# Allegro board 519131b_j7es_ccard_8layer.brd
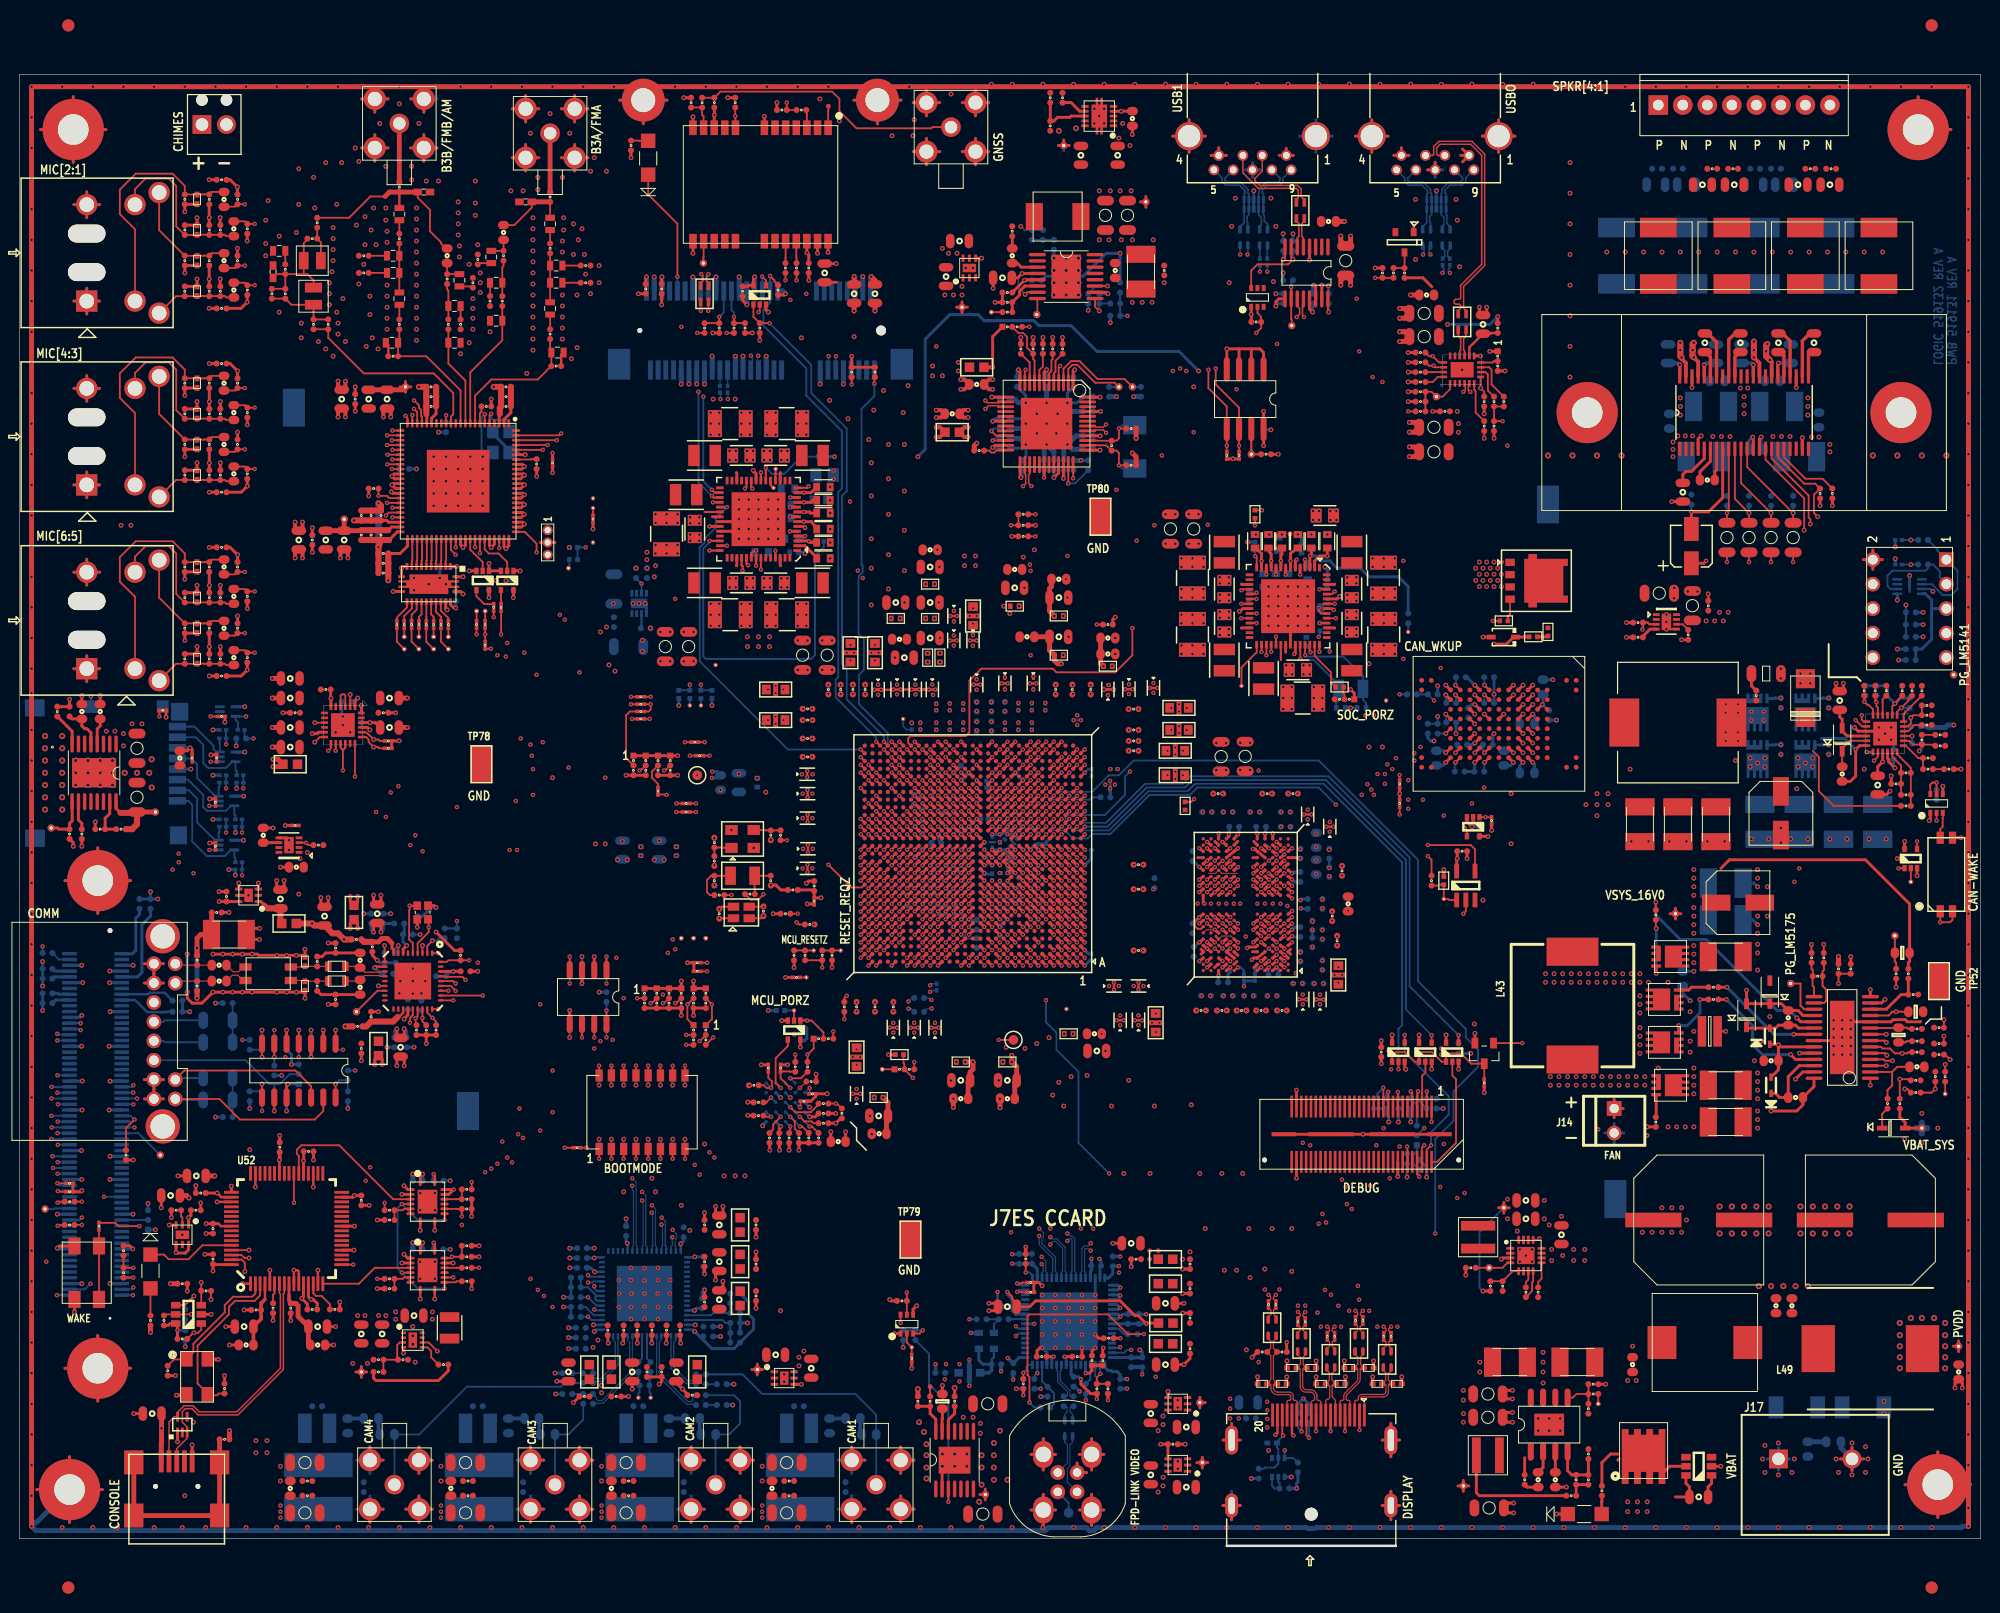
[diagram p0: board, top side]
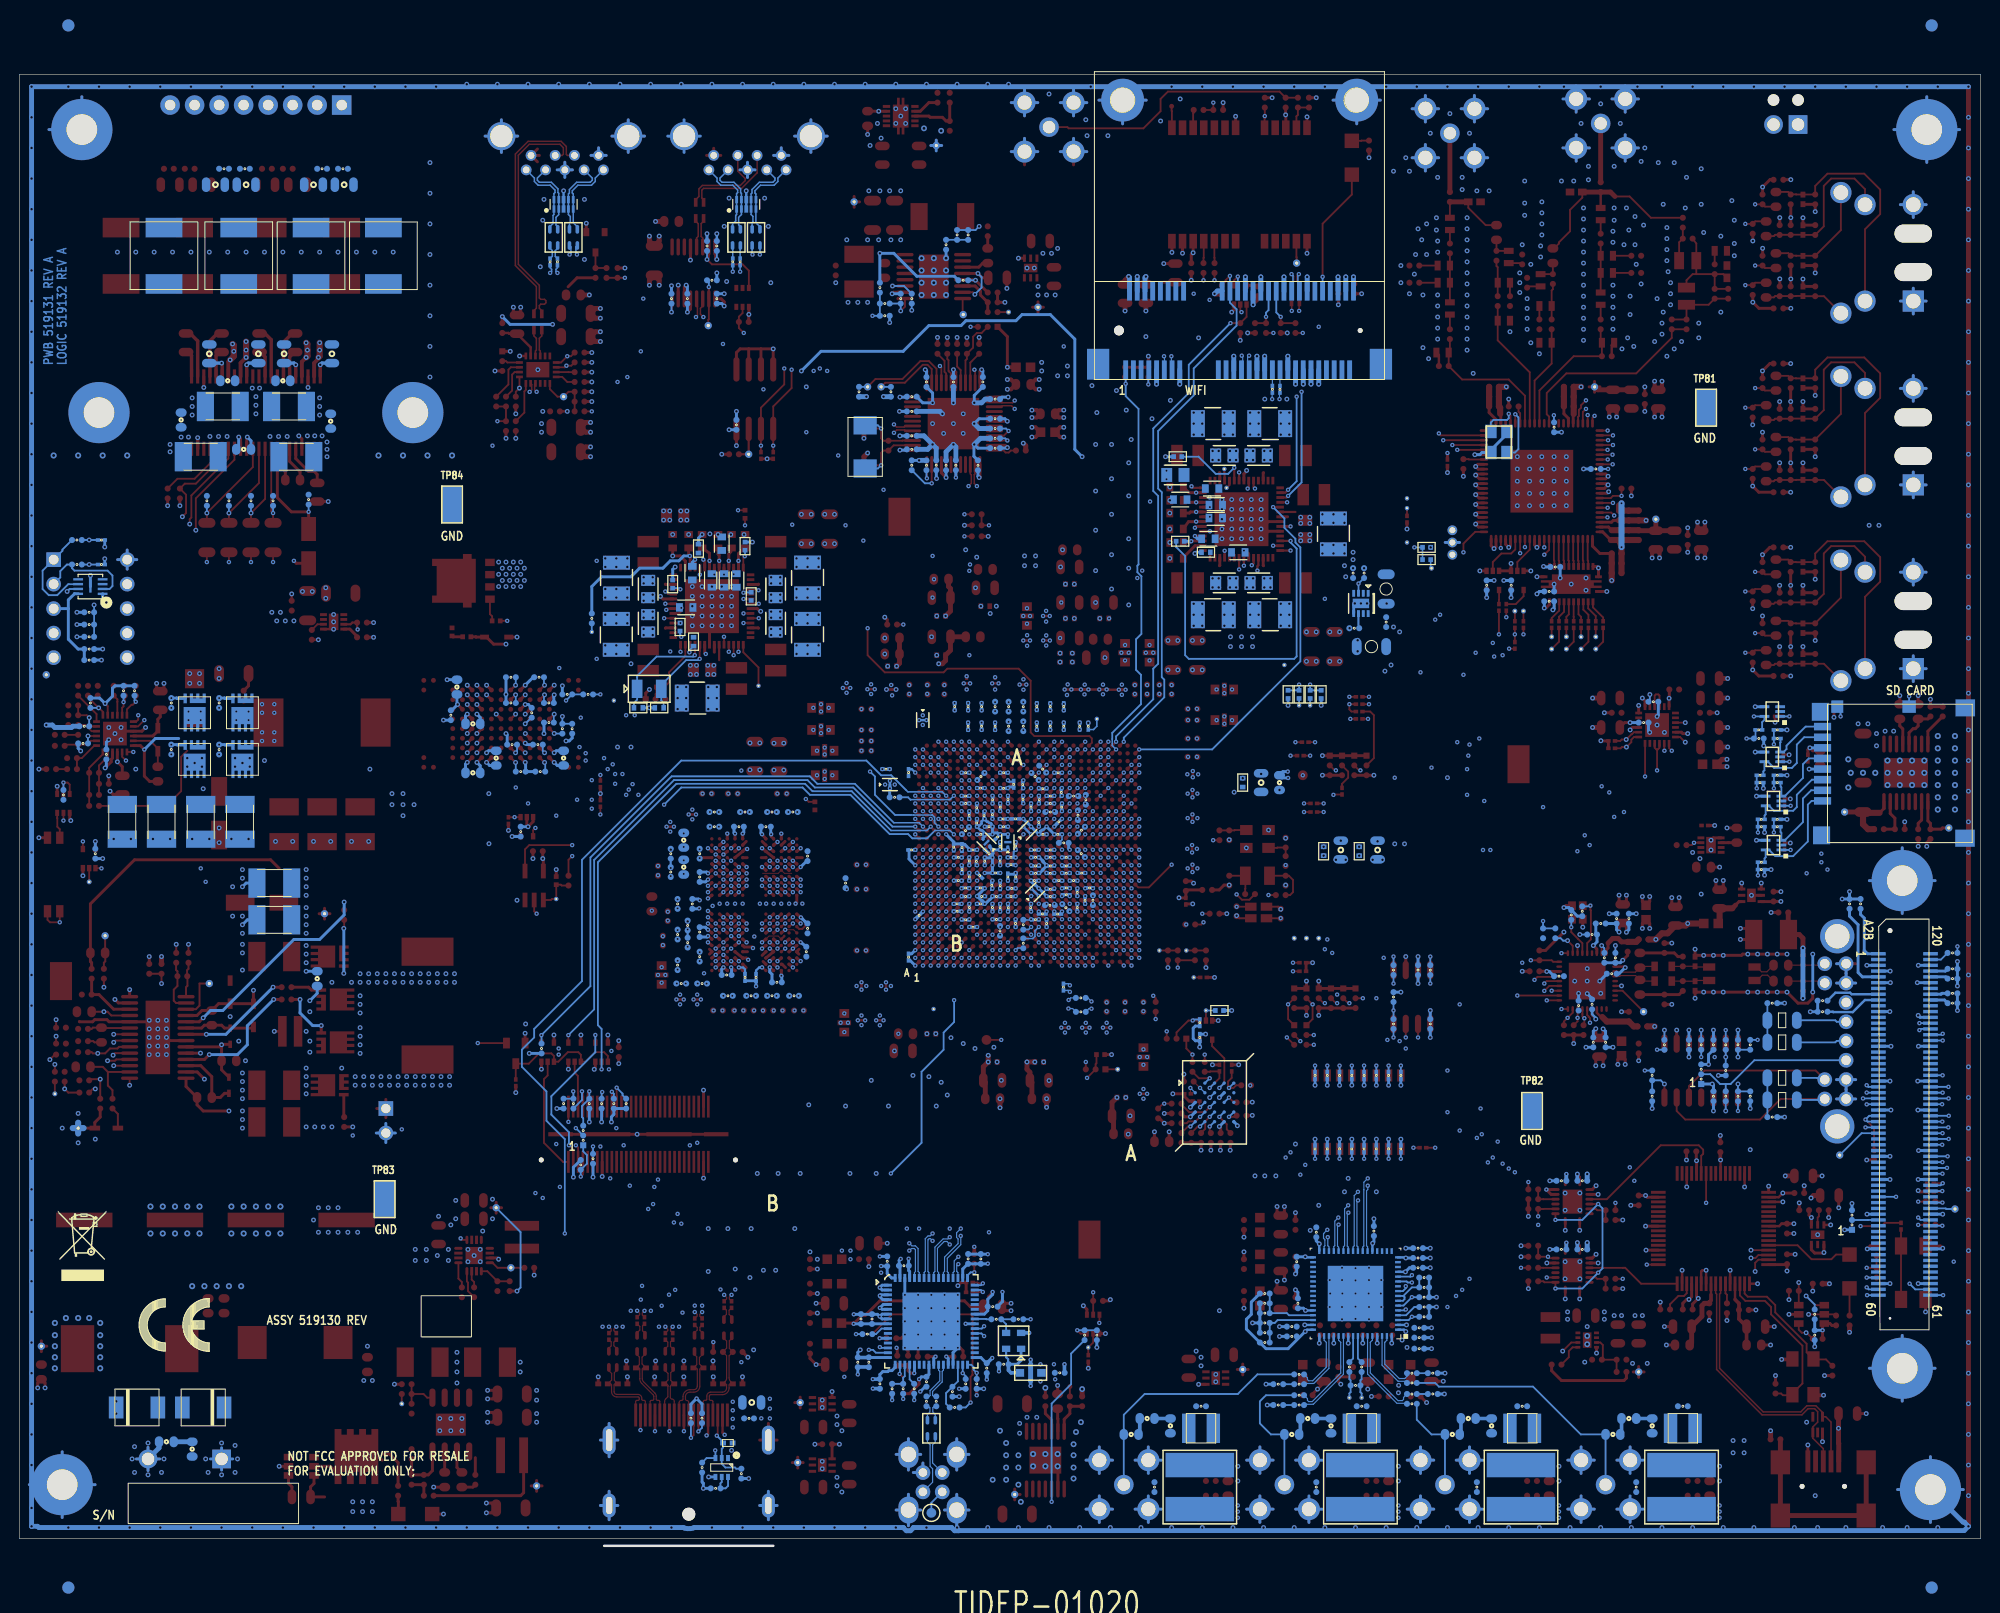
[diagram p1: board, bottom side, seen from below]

Outline 203.2 x 152.52 mm; copper layers: TOP, L2-SIGNAL, L3-GND, L4-SIGNAL, L5-SIGNAL, L6-PWR, L7-SIGNAL, BOTTOM. Coordinates in mm from the lower left corner of the outline.
Outline path: 0,152.52 0,0.75 203.2,0.75 203.2,152.52 0,152.52

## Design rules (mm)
net group C_DP0_TX0_N: nets C_DP0_TX0_N CON_DP0_TX0_N
net group C_PCIE0_TX0: nets C_PCIE0_TX0_N C_PCIE0_TX0_P
net group C_UB981_DOUT0: nets C_UB981_DOUT0_N C_UB981_DOUT0_P
net group C_USB_SS_TX1: nets C_USB1_SS_TX_N C_USB1_SS_TX_P
net group C_USB_SS_TX2: nets C_USB0_SS_TX_N C_USB0_SS_TX_P
net group CAM_0: nets CAM_0_N CAM_0_P
net group CAM_1: nets CAM_1_N CAM_1_P
net group CAM_2: nets CAM_2_N CAM_2_P
net group CAM_3: nets CAM_3_N CAM_3_P
net group CON_MMC1_CLK: nets CON_MMC1_CLK H_MMC1_CLK
net group CON_MMC1_DAT3: nets CON_MMC1_DAT3 H_MMC1_D3
net group CONN_USB1_DM: nets CONN_USB1_DM USB1_DM
net group CONN_USB1_DP: nets CONN_USB1_DP USB1_DP
net group CONN_USB2_D: nets CONN_USB2_DM CONN_USB2_DP
net group CONN_USB_RXN0: nets CONN_USB_RXN0 USB0_SS_RX2_N
net group CONN_USB_RXN1: nets CONN_USB_RXN1 USB1_SS_RX1_N
net group CONN_USB_RXP0: nets CONN_USB_RXP0 USB0_SS_RX2_P
net group CONN_USB_RXP1: nets CONN_USB_RXP1 USB1_SS_RX1_P
net group CONN_USB_TXN0: nets CONN_USB_TXN0 USB0_SS_TX2_N
net group CONN_USB_TXN1: nets CONN_USB_TXN1 USB1_SS_TX1_N
net group CONN_USB_TXP0: nets CONN_USB_TXP0 USB0_SS_TX2_P
net group CONN_USB_TXP1: nets CONN_USB_TXP1 USB1_SS_TX1_P
net group CSI0_RXCLK: nets CSI0_RXCLK_N CSI0_RXCLK_P
net group DP_H_USB2_D: nets USB1_DATA_N USB1_DATA_P
net group DP_USB_DN1: nets USB1_HUB_D_N USB1_HUB_D_P
net group FPD_DOUT0_N: nets FPD_DOUT0_N UB981_DOUT0_N
net group FPD_DOUT0_P: nets FPD_DOUT0_P UB981_DOUT0_P
net group H_MMC1_CMD: nets CON_MMC1_CMD H_MMC1_CMD
net group H_MMC1_D0: nets CON_MMC1_DAT0 H_MMC1_D0
net group H_MMC1_D1: nets CON_MMC1_DAT1 H_MMC1_D1
net group H_MMC1_D2: nets CON_MMC1_DAT2 H_MMC1_D2
net group MCASP1_ACLKX_BOOTMODE6: nets MCASP1_ACLKX_BOOTMODE6 TUNER_AUDIO_ACLKX
net group MCASP1_AFSX: nets MCASP1_AFSX TUNER_AUDIO_FSX
net group MCU_OSPI0_DQS: nets MCU_OSPI0_DQS OSPI_DQS_R
net group MMC0_DS: nets MMC0_DS N28964551
net group PCIE0_REFCLK: nets PCIE0_REFCLK_N PCIE0_REFCLK_P
net group PCIE0_RX0: nets PCIE0_RX0_N PCIE0_RX0_P
net group PCIE0_TX0: nets PCIE0_TX0_N PCIE0_TX0_P
net group PCIE0_USB_D+: nets N29483068 PCIE0_USB_D+
net group PCIE0_USB_D-: nets N29483119 PCIE0_USB_D-
net group TRD1_N: nets N33657370 TRD1_N
net group TRD1_P: nets N33657272 TRD1_P
net group TRD_N: nets N31251611 TRD_N
net group TRD_P: nets N31252401 TRD_P
net group TUNER0_IQ_ACLKR: nets N30029920 TUNER0_IQ_ACLKR
net group TUNER0_IQ_AXR0: nets N30029914 TUNER0_IQ_AXR0
net group TUNER0_IQ_AXR1: nets N30029917 TUNER0_IQ_AXR1
net group TUNER0_IQ_FSR: nets N30029923 TUNER0_IQ_FSR
net group TUNER1_IQ_ACLKR: nets N30029911 TUNER1_IQ_ACLKR
net group TUNER1_IQ_AXR0: nets N30029926 TUNER1_IQ_AXR0
net group TUNER1_IQ_AXR1: nets N30029929 TUNER1_IQ_AXR1
net group TUNER1_IQ_FSR: nets N30029908 TUNER1_IQ_FSR
net group TUNER_AUDIO: nets TUNER_AUDIO_AXR0 TUNER_AUDIO_AXR1
net group TUNER_SPI_SCLK: nets SPI6_CLK_BOOTMODE1 TUNER_SPI_SCLK
net group USB0_DATA: nets USB0_DATA_N USB0_DATA_P
net group USB2_D: nets USB2_DM USB2_DP
net group USB_90: nets USART_DM USART_DP
net group 50-OHM_PH: nets LPDDR4_CA0 LPDDR4_CA1 LPDDR4_CA2 LPDDR4_CA3 LPDDR4_CA4 LPDDR4_CA5 LPDDR4_DM0_DBI0# LPDDR4_DM1_DBI1# LPDDR4_DM2_DBI2# LPDDR4_DM3_DBI3# LPDDR4_DQ0 LPDDR4_DQ1 LPDDR4_DQ2 LPDDR4_DQ3 LPDDR4_DQ4 LPDDR4_DQ5 LPDDR4_DQ6 LPDDR4_DQ7 LPDDR4_DQ8 LPDDR4_DQ9 LPDDR4_DQ10 LPDDR4_DQ11 LPDDR4_DQ12 LPDDR4_DQ13 LPDDR4_DQ14 LPDDR4_DQ15 LPDDR4_DQ16 LPDDR4_DQ17 LPDDR4_DQ18 LPDDR4_DQ19 LPDDR4_DQ20 LPDDR4_DQ21 LPDDR4_DQ22 LPDDR4_DQ23 LPDDR4_DQ24 LPDDR4_DQ25 LPDDR4_DQ26 LPDDR4_DQ27 LPDDR4_DQ28 LPDDR4_DQ29 LPDDR4_DQ30 LPDDR4_DQ31 LPDDR4_ODT_CA_A LPDDR4_ODT_CA_B LPDDR4_RST#
net group 90-OHM_PH: nets LPDDR4_CK_C LPDDR4_CK_T LPDDR4_DQS0_N LPDDR4_DQS0_P LPDDR4_DQS1_N LPDDR4_DQS1_P LPDDR4_DQS2_N LPDDR4_DQS2_P LPDDR4_DQS3_N LPDDR4_DQS3_P
net group 100-OHM_PH: nets DP0_TX0_N MCU_OSPI0_CLK_N MCU_OSPI0_CLK_P
net group C_DP0_AUX_N: nets C_DP0_AUX_N CON_DP0_AUX_N DP0_AUX_N
net group C_DP0_AUX_P: nets C_DP0_AUX_P CON_DP0_AUX_P DP0_AUX_P
net group C_DP0_TX0_P: nets C_DP0_TX0_P CON_DP0_TX0_P DP0_TX0_P
net group C_DP0_TX1_N: nets C_DP0_TX1_N CON_DP0_TX1_N DP0_TX1_N
net group C_DP0_TX1_P: nets C_DP0_TX1_P CON_DP0_TX1_P DP0_TX1_P
net group C_DP0_TX2_N: nets C_DP0_TX2_N CON_DP0_TX2_N DP0_TX2_N
net group C_DP0_TX2_P: nets C_DP0_TX2_P CON_DP0_TX2_P DP0_TX2_P
net group C_DP0_TX3_N: nets C_DP0_TX3_N CON_DP0_TX3_N DP0_TX3_N
net group C_DP0_TX3_P: nets C_DP0_TX3_P CON_DP0_TX3_P DP0_TX3_P
net group CSI0_RX: nets CSI0_RX0_N CSI0_RX0_P CSI0_RX1_N CSI0_RX1_P CSI0_RX2_N CSI0_RX2_P CSI0_RX3_N CSI0_RX3_P
net group DDR4_CK: nets LPDDR4_CSN0_0 LPDDR4_CSN0_1 LPDDR4_CSN1_0 LPDDR4_CSN1_1
net group DSI0_TX: nets DSI0_TX0_N DSI0_TX0_P DSI0_TX1_N DSI0_TX1_P DSI0_TX2_N DSI0_TX2_P DSI0_TX3_N DSI0_TX3_P DSI0_TXCLK_N DSI0_TXCLK_P
net group MCU_OSPI0_CLK_N: nets SOC_MCU_OSPI0_LBCLKO_R
net group MCU_OSPI0_CLK_P: nets SOC_MCU_OSPI0_CLK_R
net group MMC0: nets MMC0_CMD MMC0_DAT0 MMC0_DAT1 MMC0_DAT2 MMC0_DAT3 MMC0_DAT4 MMC0_DAT5 MMC0_DAT6 MMC0_DAT7
net group MMC0_CLK: nets MMC0_CLK N22073312 N29500526
net group OSPI0: nets MCU_OSPI0_CS0# MCU_OSPI0_D0 MCU_OSPI0_D1 MCU_OSPI0_D2 MCU_OSPI0_D3 MCU_OSPI0_D4 MCU_OSPI0_D5 MCU_OSPI0_D6 MCU_OSPI0_D7
net group PWR: nets G720_VDD1A G720_VDD1B G720_VDDIO G720_VSLEEP
net group PWR_PH: nets V3V3_DP0 VCAP_MCU_VDDS0 VCAP_MCU_VDDS1 VCAP_MCU_VDDS2 VCAP_VDDS0 VCAP_VDDS1 VCAP_VDDS2 VCAP_VDDS3 VCAP_VDDS4 VCAP_VDDS5 VCAP_VDDS6 VCC_APL VCC_LM5141 VCC_LM5175 VDA_MCU_1V8 VDA_PLL_1V8 VDD18_DSI VDD_CORE_RAM_0V85 VDD_CPU_RAM_0V85 VDD_DSI_OSC VDD_MCU_RAM_0V85 VDD_MCUIO_1V8 VDD_SPK VDD_TAS VDDA_0P8_CSIRX VDDA_0P8_PLL_DDR VDDA_0P8_UFS VDDA_1P8_CSI_RX VDDA_1P8_SERDES VDDA_1P8_UFS VDDA_LM5141 VDDHS11_DSI VDDI_MMC2 VDDL11_DSI VDDP11_DSI VEXP_1V8A VEXP_1V8B VEXP_3V3A VEXP_3V3B VEXP_5V0A VEXP_5V0B VEXP_5V0C VEXP_5V0D VINT_LEOA_1V8 VINT_LEOB_1V8 VMON_VEXT VMON_VSYS VOSNS VPHY_USART VPLL_USART VPP_EFUSE_1V8 VRTC_LEOA_1V8 VRTC_LEOB_1V8 VSYS_SENSE VTUN_1V8
net group RGMII5_RX: nets RGMII5_RD3 RGMII5_RX_CTL RGMII5_RXC
net group RGMII5_TX: nets RGMII5_TD0 RGMII5_TD1 RGMII5_TD2 RGMII5_TD3 RGMII5_TX_CTL RGMII5_TXC
net group TUNER_AUDIO_AXR10: nets DOUT0 N29203584 TUNER_AUDIO_AXR10
net group TUNER_AUDIO_AXR11: nets DOUT1 N29203608 TUNER_AUDIO_AXR11
net group TUNER_SPI: nets TUNER_SPI_CS0 TUNER_SPI_D0 TUNER_SPI_D1

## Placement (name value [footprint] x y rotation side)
C1  560pF  [C402-25]  108.08 150.1 270 top
C2  0  [C402-25]  70.74 149.6 90 top
C3  1uF  [C603-35X45]  115.32 147.94 270 top
C4  4.7uF  [C805-35X60]  109.98 144.13 90 top
C5  4.7uF  [C805-35X60]  113.79 144.13 90 top
C6  1nF  [C402-25]  175.39 142.74 180 top
C7  1nF  [C402-25]  177.55 142.74 0 top
C8  1nF  [C402-25]  185.55 142.74 180 top
C9  1nF  [C402-25]  187.71 142.74 0 top
C10  0.1uF  [C402-25RD]  20.95 141.59 0 top
C11  1uF  [C805-35X60]  174.37 141.09 0 top
C12  1uF  [C805-35X60]  177.67 141.09 180 top
C13  1uF  [C805-35X60]  184.28 141.09 0 top
C14  1uF  [C805-35X60]  187.58 141.09 180 top
C15  1uF  [C402-25]  39.37 140.83 90 top
C16  1uF  [C402-25]  54.99 139.82 90 top
C17  1000pF  [C402-25]  17.14 139.56 90 top
C18  10uF  [C603-35X45]  21.21 139.56 90 top
C19  10uF  [C1206-40X70]  112.52 137.91 270 top
C20  10uF  [C1206-40X70]  114.81 137.91 270 top
C21  0.1uF  [C603-35X45]  135.64 137.28 180 top
C22  82pF  [C402-25]  30.86 137.15 270 top
C23  10uF  [C603-35X45]  22.23 136.51 270 top
C24  1000pF  [C402-25]  17.14 136.39 90 top
C25  20pF  [C603-35X45]  50.16 136.13 90 top
C26  3.6pF  [C402-25]  30.35 135.5 0 top
C27  1nF  [C402-25]  39.37 135.5 90 top
C28  4.7uF  [C805-35X60]  97.41 135.24 180 top
C29  1nF  [C402-25]  54.99 134.48 90 top
C30  43pF  [C402-25]  35.69 133.72 180 top
C31  20pF  [C603-35X45]  44.32 133.72 90 top
C32  11pF  [C402-25]  50.16 133.72 90 top
C33  1uF  [C603-35X45]  102.87 133.72 90 top
C34  36pF  [C402-25]  47.5 133.34 90 top
C35  1000pF  [C402-25]  17.14 133.21 90 top
C36  10uF  [C603-35X45]  21.21 133.21 90 top
C37  10uF  [C1206-40X70]  137.41 133.21 90 top
C38  470pF  [C402-25]  58.67 132.7 0 top
C39  0.1uF  [C402-25]  81.79 132.45 270 top
C40  7.0pF  [C402-25]  27.56 132.32 90 top
C41  0.1uF  [C603-35X45]  113.54 132.2 270 top
C42  0.01uF  [C402-25]  118.62 132.2 270 top
C43  10uF  [C1210-70X102]  116.2 132.07 90 top
C44  470pF  [C402-25]  35.69 131.94 180 top
C45  10uF  [C805-35X60]  83.44 131.94 270 top
C46  4.7uF  [C805-35X60]  96.01 131.56 270 top
C47  4.7uF  [C805-35X60]  101.85 131.43 0 top
C48  11pF  [C402-25]  44.32 131.31 90 top
C49  36pF  [C402-25]  46.99 130.93 90 top
C50  43pF  [C402-25]  58.67 130.93 0 top
C51  0.1uF  [C402-25]  64.9 130.29 270 top
C52  0.1uF  [C402-25]  66.55 130.29 270 top
C53  10uF  [C603-35X45]  22.23 130.16 270 top
C54  1000pF  [C402-25]  17.14 130.04 90 top
C55  0.1uF  [C402-25]  74.93 130.04 90 top
C56  0.1uF  [C402-25RD]  102.36 129.91 180 top
C57  1pF  [C402-25]  27.56 129.78 90 top
C58  10uF  [C805-35X60]  86.49 129.78 270 top
C59  10uF  [C805-35X60]  88.65 129.78 270 top
C60  0.1uF  [C603-35X45]  145.8 129.66 0 top
C61  680pF  [C402-25]  48.77 129.02 270 top
C62  13pF  [C402-25]  50.04 129.02 90 top
C63  0.1uF  [C402-25RD]  20.95 128.26 0 top
C64  1000pF  [C402-25]  102.36 127.88 180 top
C65  10uF  [C1206-40X70]  145.54 127.75 180 top
C66  2200pF  [C402-25]  30.48 126.61 90 top
C67  22pF  [C402-25]  39.37 126.61 90 top
C68  13pF  [C402-25]  44.45 126.61 90 top
C69  680pF  [C402-25]  45.72 126.61 270 top
C70  2.2uF  [C805-35X60]  151.64 126.61 90 top
C71  22pF  [C402-25]  54.99 125.59 90 top
C72  10uF  [C1206-40X70]  145.54 125.34 180 top
C73  1uF  [C805-35X60]  174.62 124.7 270 top
C74  1uF  [C805-35X60]  178.31 124.7 270 top
C75  1uF  [C805-35X60]  182.25 124.7 270 top
C76  1uF  [C805-35X60]  185.93 124.7 270 top
C77  43pF  [C402-25]  38.73 123.31 180 top
C78  0.1uF  [C402-25RD]  20.95 122.54 0 top
C79  43pF  [C402-25]  55.63 122.29 0 top
C80  1000pF  [C402-25]  17.14 120.51 90 top
C81  10uF  [C603-35X45]  21.21 120.51 90 top
C82  10uF  [C603-35X45]  99.19 120.39 180 top
C83  1uF  [C402-25]  42.67 120.13 180 top
C84  1uF  [C402-25]  50.42 120.13 180 top
C85  2.2nF  [C402-25]  42.67 119.12 180 top
C86  2.2nF  [C402-25]  50.42 119.12 180 top
C87  10uF  [C805-35X60]  33.4 118.86 90 top
C88  0.1uF  [C402-25RD]  34.8 118.86 90 top
C89  10uF  [C805-35X60]  38.1 118.86 270 top
C90  0.1uF  [C402-25]  145.16 118.61 180 top
C91  18pF  [C402-25]  42.67 118.1 180 top
C92  1uF  [C402-25]  48.39 118.1 180 top
C93  18pF  [C402-25]  50.42 118.1 180 top
C94  0.1uF  [C402-25]  147.7 117.59 180 top
C95  10uF  [C603-35X45]  22.23 117.46 270 top
C96  1000pF  [C402-25]  17.14 117.34 90 top
C97  1uF  [C603-35X45]  96.65 117.34 180 top
C98  47uF  [CAP1210_2-75]  73.66 116.32 0 top
C99  47uF  [CAP1210_2-75]  79.5 116.32 180 top
C100  10uF  [C1206-40X70]  146.56 115.94 180 top
C101  27 pF  [C402-25]  115.19 115.81 0 top
C102  1000pF  [C402-25]  17.14 114.16 90 top
C103  10uF  [C603-35X45]  21.21 114.16 90 top
C104  10uF  [C1206-40X70]  146.56 113.4 180 top
C105  10uF  [CAP0805_1-5]  74.8 113.02 0 top
C106  10uF  [CAP0805_1-5]  78.36 113.02 180 top
C107  27 pF  [C402-25]  115.19 112 0 top
C108  10uF  [C603-35X45]  22.23 111.11 270 top
C109  1000pF  [C402-25]  17.14 110.99 90 top
C110  1uF  [C603-35X45]  174.88 110.48 0 top
C111  2.2uF  [CAP0603_1]  83.3 109.74 0 top
C112  0.1uF  [C402-25RD]  20.95 109.21 0 top
C113  2.2uF  [C805-35X60]  172.34 109.21 270 top
C114  2.2uF  [CAP0603_1]  83.3 108.37 0 top
C115  2.2uF  [CAP0603_1]  83.31 107.05 0 top
C116  1uF  [C402-25]  35.43 106.8 90 top
C117  2.2nF  [C402-25]  36.45 106.8 90 top
C118  18pF  [C402-25]  37.47 106.8 90 top
C119  10uF  [CAP0805_1-5]  135.25 106.8 180 top
C120  10uF  [CAP0805_1-5]  69.98 105.4 270 top
C121  2.2uF  [CAP0603_1]  83.31 105.4 0 top
C122  47uF  [C1206-40X70]  119.25 105.4 90 top
C123  47uF  [C1206-40X70]  121.67 105.4 90 top
C124  47uF  [CAP1210_2-75]  67.06 104.89 270 top
C125  1uF  [C402-25]  35.43 104.76 270 top
C126  2.2nF  [C402-25]  36.45 104.76 270 top
C127  18pF  [C402-25]  37.47 104.76 270 top
C128  0.47uF  [C1206-40X70]  176.91 104.51 270 top
C129  0.47uF  [C1206-40X70]  179.2 104.51 270 top
C130  0.47uF  [C1206-40X70]  181.48 104.51 270 top
C131  0.47uF  [C1206-40X70]  183.77 104.51 270 top
C132  10uF  [C805-35X60]  28.96 104.26 90 top
C133  0.1uF  [C402-25RD]  30.35 104.26 90 top
C134  10uF  [C805-35X60]  33.66 104.26 270 top
C135  2.2uF  [CAP0603_1]  128.02 104.13 90 top
C136  2.2uF  [CAP0603_1]  129.41 104.13 90 top
C137  2.2uF  [CAP0603_1]  130.81 104.13 90 top
C138  2.2uF  [CAP0603_1]  132.46 104.13 90 top
C139  2.2uF  [CAP0603_1]  133.86 104.13 90 top
C140  2.2uF  [CAP0603_1]  135.51 104.13 90 top
C141  2.2uF  [CAP0603_1]  83.31 104 0 top
C142  2.2uF  [CAPAE_B4CASE]  173.23 103.62 90 top
C143  0.1uF  [C402-25RD]  20.95 103.49 0 top
C144  18pF  [C402-25]  37.72 102.86 180 top
C145  2.2uF  [CAP0603_1]  83.31 102.35 0 top
C146  2.2nF  [C402-25]  37.72 101.84 180 top
C147  1000pF  [C402-25]  17.14 101.46 90 top
C148  10uF  [C603-35X45]  21.21 101.46 90 top
C149  22uF  [C805-35X60]  94.36 101.46 0 top
C150  1uF  [C402-25]  37.72 100.83 180 top
C151  47uF  [CAP1210_2-75]  121.54 100.32 270 top
C152  47uF  [CAP1210_2-75]  141.33 100.31 270 top
C153  10uF  [CAP0805_1-5]  74.8 99.81 0 top
C154  10uF  [CAP0805_1-5]  78.36 99.81 180 top
C155  1uF  [CAP0402_0-75]  94.36 99.68 0 top
C156  22uF  [C805-35X60]  103.12 99.3 0 top
C157  10uF  [CAP0805_1-5]  124.84 99.18 270 top
C158  10uF  [CAP0805_1-5]  138.05 99.18 270 top
C159  22uF  [C1206-40X70]  169.9 98.75 0 top
C160  10uF  [C603-35X45]  22.23 98.41 270 top
C161  1000pF  [C402-25]  17.14 98.29 90 top
C162  22uF  [C805-35X60]  107.7 98.29 0 top
C163  22uF  [C805-35X60]  90.81 97.78 0 top
C164  22uF  [C805-35X60]  94.36 97.78 0 top
C165  22uF  [C1206-40X70]  173.33 97.45 90 top
C166  0.1uF  [C402-25]  174.98 97.45 90 top
C167  1uF  [CAP0402_0-75]  103.12 97.4 0 top
C168  47uF  [CAP1210_2-75]  73.66 96.51 0 top
C169  47uF  [CAP1210_2-75]  79.5 96.51 180 top
C170  1uF  [EMIFIL_NFM15CC_0402_0-5]  96.82 96.38 270 top
C171  10uF  [NFM18HC]  98.81 96.38 270 top
C172  1uF  [CAP0402_0-75]  107.7 96.38 0 top
C173  1uF  [CAP0402_0-75]  90.81 96.13 0 top
C174  1uF  [CAP0402_0-75]  94.36 96.13 0 top
C175  10uF  [CAP0805_1-5]  124.84 95.62 90 top
C176  10uF  [CAP0805_1-5]  138.05 95.62 90 top
C177  1000pF  [C402-25]  17.14 95.11 90 top
C178  10uF  [C603-35X45]  21.21 95.11 90 top
C179  47uF  [CAP1210_2-75]  121.54 94.48 90 top
C180  47uF  [CAP1210_2-75]  141.35 94.48 90 top
C181  220pF  [C402-25]  172.9 94.43 270 top
C182  22uF  [C805-35X60]  107.7 94.22 0 top
C183  0.1uF  [C402-25]  167.7 94.17 180 top
C184  22uF  [C805-35X60]  94.36 94.1 0 top
C185  1uF  [EMIFIL_NFM15CC_0402_0-5]  96.81 93.84 270 top
C186  1uF  [EMIFIL_NFM15CC_0402_0-5]  98.81 93.84 270 top
C187  47uF  [C1206-40X70]  66.93 93.21 90 top
C188  47uF  [C1206-40X70]  69.34 93.21 90 top
C189  10uF  [NFM18HC]  86.11 92.57 270 top
C190  10uF  [NFM18HC]  88.65 92.57 270 top
C191  10uF  [C603-35X45]  112.78 92.45 0 top
C192  47uF  [C1206-40X70]  81.15 92.32 90 top
C193  47uF  [C1206-40X70]  83.69 92.32 90 top
C194  1uF  [CAP0402_0-75]  107.7 92.32 0 top
C195  10uF  [C603-35X45]  22.23 92.06 270 top
C196  22uF  [C805-35X60]  91.69 92.06 180 top
C197  1uF  [CAP0402_0-75]  94.11 92.06 90 top
C198  1uF  [CAP0402_0-75]  95.38 92.06 90 top
C199  1000pF  [C402-25]  17.14 91.94 90 top
C200  1uF  [CAP0402_0-75]  112.78 91.18 0 top
C201  10uF  [CAP0805_1-5]  132.46 90.79 0 top
C202  0.1uF  [C402-25RD]  20.95 90.16 0 top
C203  10uF  [C805-35X60]  28.07 89.91 180 top
C204  1uF  [EMIFIL_NFM15CC_0402_0-5]  102.11 89.4 270 top
C205  1uF  [EMIFIL_NFM15CC_0402_0-5]  105.05 89.4 270 top
C206  1uF  [EMIFIL_NFM15CC_0402_0-5]  99.19 89.27 270 top
C207  1uF  [EMIFIL_NFM15CC_0402_0-5]  117.5 88.92 270 top
C208  1uF  [EMIFIL_NFM15CC_0402_0-5]  114.96 88.79 270 top
C209  0.1uF  [C402-25]  31.75 88.76 0 top
C210  10uF  [NFM18HC]  78.36 88.76 0 top
C211  0.47uF  [C402-25]  83.82 88.76 90 top
C212  0.47uF  [C402-25]  85.09 88.76 90 top
C213  0.47uF  [C402-25]  86.36 88.76 90 top
C214  0.47uF  [C402-25]  87.63 88.76 90 top
C215  1uF  [EMIFIL_NFM15CC_0402_0-5]  90.93 88.76 270 top
C216  1uF  [EMIFIL_NFM15CC_0402_0-5]  92.82 88.76 270 top
C217  1uF  [EMIFIL_NFM15CC_0402_0-5]  94.59 88.76 270 top
C218  0.47uF  [C402-25]  107.37 88.76 90 top
C219  0.47uF  [C402-25]  109.09 88.76 90 top
C220  0.47uF  [C402-25]  111 88.76 90 top
C221  1uF  [EMIFIL_NFM15CC_0402_0-5]  112.78 88.76 90 top
C222  1uF  [EMIFIL_NFM15CC_0402_0-5]  88.97 88.74 270 top
C223  0.01uF  [C402-25]  192.28 88.64 270 top
C224  0.1uF  [C402-25]  195.07 88.64 90 top
C225  0.01uF  [C402-25]  197.1 88.64 270 top
C226  1000pF  [C402-25]  179.96 88.13 270 top
C227  10uF  [C805-35X60]  28.07 87.87 180 top
C228  10uF  [C805-35X60]  38.35 87.87 0 top
C229  47uF  [CAP1210_2-75]  132.97 87.87 0 top
C230  4.7uF  [C805-35X60]  188.59 87.62 90 top
C231  1uF  [EMIFIL_NFM15CC_0402_0-5]  100.79 72.94 90 bottom
C232  10uF  [NFM18HC]  120.14 86.86 180 top
C233  0.47uF  [C402-25]  81.66 86.76 180 top
C234  0.47uF  [C402-25]  115.44 86.73 0 top
C235  1uF  [C603-35X45]  6.48 86.48 90 top
C236  1uF  [C603-35X45]  8.38 86.48 90 top
C237  0.1uF  [C402-25]  28.57 86.35 180 top
C238  0.1uF  [C402-25]  37.72 86.35 0 top
C239  0.01uF  [C402-25]  197.61 86.1 180 top
C240  0.1uF  [C201-6P6SPC]  20.95 85.97 0 top
C241  10uF  [NFM18HC]  78.36 85.59 0 top
C242  0.47uF  [C402-25]  81.66 85.59 180 top
C243  0.047uF  [C402-25]  197.61 85.08 180 top
C244  10uF  [C805-35X60]  28.07 84.83 180 top
C245  10uF  [C805-35X60]  38.35 84.83 0 top
C246  0.47uF  [C402-25]  115.44 84.57 0 top
C247  1uF  [EMIFIL_NFM15CC_0402_0-5]  103 72.89 45 bottom
C248  10uF  [NFM18HC]  120.14 84.57 180 top
C249  0.033uF  [C402-25]  199.01 84.06 180 top
C250  0.47uF  [C402-25]  81.66 83.68 180 top
C251  68pF  [C402-25]  199.01 82.92 0 top
C252  10uF  [C805-35X60]  28.07 82.79 180 top
C253  10uF  [C1206-40X70]  12.19 82.67 270 top
C254  0.47uF  [C402-25]  115.44 82.41 0 top
C255  10uF  [NFM18HC]  119.76 82.41 180 top
C256  47uF  [C1206-40X70]  127 81.83 270 top
C257  47uF  [C1206-40X70]  124.51 81.8 270 top
C258  0.47uF  [C402-25]  81.66 81.78 180 top
C259  10uF  [C603-35X45]  16.64 81.65 90 top
C260  0.1uF  [C201-6P6SPC]  17.91 81.65 90 top
C261  0.1uF  [C201-6P6SPC]  20.45 81.65 90 top
C262  0.1uF  [C402-25]  195.45 80.13 0 top
C263  0.1uF  [C603-35X45]  188.85 80 90 top
C264  1uF  [EMIFIL_NFM15CC_0402_0-5]  81.62 79.98 0 top
C265  10uF  [NFM18HC]  119.76 79.87 180 top
C266  1uF  [C805-35X60]  192.53 78.86 270 top
C267  1uF  [EMIFIL_NFM15CC_0402_0-5]  98.78 74.13 135 bottom
C268  1uF  [EMIFIL_NFM15CC_0402_0-5]  81.66 77.97 0 top
C269  0.01uF  [C402-25]  124.21 77.97 0 top
C270  0.1uF  [C402-25]  129.29 77.97 0 top
C271  0.47uF  [C402-25]  131.95 77.97 0 top
C272  10uF  [C1206-40X70]  12.19 77.59 90 top
C273  0.1uF  [C201-6P6SPC]  20.32 77.08 90 top
C274  120uF  [CAP-FK-D8-65X117]  182.5 75.94 0 top
C275  1uF  [EMIFIL_NFM15CC_0402_0-5]  133.48 75.81 90 top
C276  1uF  [EMIFIL_NFM15CC_0402_0-5]  97.97 67.76 135 bottom
C277  1uF  [EMIFIL_NFM15CC_0402_0-5]  81.66 75.43 0 top
C278  22uF  [C1210-70X102]  167.89 74.79 270 top
C279  22uF  [C1210-70X102]  171.83 74.79 270 top
C280  22uF  [C1210-70X102]  175.77 74.79 270 top
C281  0.1uF  [C201-6P6SPC]  28.57 74.67 180 top
C282  1uF  [EMIFIL_NFM15CC_0402_0-5]  135.76 74.54 90 top
C283  NP  [C603-35X45]  25.27 73.65 90 top
C284  30pF  [C402-25]  77.85 73.65 270 top
C285  30pF  [C402-25]  72.01 72.89 90 top
C286  0.1uF  [C201-6P6SPC]  20.32 72.51 90 top
C287  1uF  [EMIFIL_NFM15CC_0402_0-5]  81.7 72.25 0 top
C288  0.47uF  [C402-25]  115.95 70.6 0 top
C289  10uF  [C603-35X45]  28.7 70.35 180 top
C290  1uF  [EMIFIL_NFM15CC_0402_0-5]  81.66 70.22 0 top
C291  0.47uF  [C402-25]  137.03 69.97 270 top
C292  9pF  [C402-25]  72.01 68.95 270 top
C293  9pF  [C402-25]  77.85 68.95 270 top
C294  0.47uF  [C402-25]  115.95 68.06 0 top
C295  100nF  [C402-25]  21.46 67.3 90 top
C296  10uF  [C805-35X60]  27.05 67.05 90 top
C297  0.1uF  [C201-6P6SPC]  82.35 66.82 270 top
C298  120uF  [CAP-FK-D8-65X117]  178.05 66.66 90 top
C299  10uF  [C603-35X45]  137.67 66.54 270 top
C300  12pF  [C402-25]  77.09 65.78 270 top
C301  10uF  [C805-35X60]  37.08 65.52 90 top
C302  12pF  [C402-25]  72.52 65.52 90 top
C303  10uF  [C805-35X60]  31.62 65.27 90 top
C304  0.47uF  [C402-25]  136.02 65.27 270 top
C305  4.7nF  [C1210-70X102]  21.72 63.36 180 top
C306  0.47uF  [C402-25]  136.53 62.73 270 top
C307  NP-100nF  [C402-25]  36.58 62.09 270 top
C308  47pF  [C402-25]  32.77 61.97 90 top
C309  0.47uF  [C402-25]  115.95 61.71 0 top
C310  10uF  [C1210-70X102]  176.78 61.08 0 top
C311  22pF  [C603-35X45]  35.31 60.7 90 top
C312  0.1uF  [C603-35X45]  20.7 60.19 0 top
C313  0.047uF  [C402-25RD]  189.74 59.81 270 top
C314  10uF  [NFM18HC]  136.65 59.17 90 top
C315  220pF  [C402-25]  186.31 59.04 180 top
C316  0.1uF  [C603-35X45]  20.7 58.54 0 top
C317  1uF  [EMIFIL_NFM15CC_0402_0-5]  113.41 58.03 0 top
C318  1uF  [EMIFIL_NFM15CC_0402_0-5]  115.95 58.03 180 top
C319  22pF  [C603-35X45]  35.31 57.9 270 top
C320  100pF  [C402-25]  196.22 57.14 180 top
C321  47pF  [C402-25]  32.77 56.63 270 top
C322  1uF  [EMIFIL_NFM15CC_0402_0-5]  132.97 56.63 90 top
C323  1uF  [EMIFIL_NFM15CC_0402_0-5]  134.75 56.63 90 top
C324  0.47uF  [C402-25]  86.74 55.87 270 top
C325  0.47uF  [C402-25]  88.65 55.87 270 top
C326  0.47uF  [C402-25]  90.55 55.87 270 top
C327  1uF  [C402-25]  122.43 55.49 0 top
C328  0.47uF  [C402-25]  124.59 55.49 0 top
C329  0.47uF  [C402-25]  126.62 55.49 0 top
C330  0.01uF  [C402-25]  128.65 55.49 0 top
C331  0.47uF  [C402-25]  130.81 55.49 0 top
C332  NP-100nF  [C402-25]  36.45 54.85 90 top
C333  0.1uF  [C603-35X45]  183.26 54.73 270 top
C334  1uF  [EMIFIL_NFM15CC_0402_0-5]  114.05 54.47 90 top
C335  1uF  [EMIFIL_NFM15CC_0402_0-5]  115.95 54.47 90 top
C336  10uF  [NFM18HC]  117.73 54.22 90 top
C337  1uF  [EMIFIL_NFM15CC_0402_0-5]  90.55 53.71 90 top
C338  1uF  [EMIFIL_NFM15CC_0402_0-5]  92.71 53.71 90 top
C339  1uF  [EMIFIL_NFM15CC_0402_0-5]  94.87 53.71 90 top
C340  0.047uF  [C402-25]  198.88 53.71 180 top
C341  1000pF  [C402-25]  196.6 53.58 0 top
C342  1uF  [CAP0402_0-75]  108.71 53.08 180 top
C343  0.022uF  [C402-25]  196.6 52.31 0 top
C344  150pF  [C402-25]  198.88 52.06 180 top
C345  10uF  [C805-35X60]  39.5 51.68 270 top
C346  NP-1uF  [C402-25]  35.43 51.55 270 top
C347  22uF  [C805-35X60]  111.63 51.3 0 top
C348  0.1uF  [C402-25]  141.1 51.17 270 top
C349  10uF  [NFM18HC]  86.74 50.66 90 top
C350  1uF  [C603-35X45]  181.48 50.28 180 top
C351  1uF  [CAP0402_0-75]  97.54 50.15 180 top
C352  1uF  [CAP0402_0-75]  102.36 50.15 180 top
C353  0.1uF  [C603-35X45]  196.6 49.65 0 top
C354  1000pF  [C402-25]  199.52 48.63 90 top
C355  22uF  [C805-35X60]  97.54 48.25 180 top
C356  22uF  [C805-35X60]  102.36 48.25 180 top
C357  100pF  [C402-25]  196.47 48.25 180 top
C358  10uF  [C1210-70X102]  176.78 47.74 0 top
C359  1uF  [EMIFIL_NFM15CC_0402_0-5]  86.74 46.85 90 top
C360  1uF  [CAP0402_0-75]  89.03 46.47 180 top
C361  0.1uF  [C603-35X45]  184.02 46.47 0 top
C362  0.1uF  [C402-25]  83.31 44.82 0 top
C363  22uF  [C805-35X60]  89.03 44.57 180 top
C364  10uF  [C1210-70X102]  176.78 43.93 0 top
C365  0.1uF  [C402-25]  78.74 42.28 270 top
C366  4.7uF  [C603-35X45]  84.84 41.9 0 top
C367  0.1uF  [C402-25]  26.97 41.32 90 top
C368  0.1uF  [C402-25]  29.97 40.88 0 top
C369  4.7uF  [C805-35X60]  18.34 38.34 180 top
C370  0.1uF  [C402-25]  18.8 36.57 180 top
C371  4.7uF  [C805-35X60]  15.67 36.31 180 top
C372  0.1uF  [C402-25]  35.43 35.8 270 top
C373  NP-22uF  [C805-35X60]  156.08 35.8 0 top
C374  0.01uF  [C402-25]  16.26 34.79 180 top
C375  0.1uF  [C402-25]  18.29 34.79 0 top
C376  470uF  [CAP-ELEC-H13]  191.77 33.77 270 top
C377  470uF  [CAP-ELEC-H13]  173.99 33.77 90 top
C378  22uF  [C805-35X60]  156.08 33.9 0 top
C379  1uF  [C402-25]  70.99 33.26 90 top
C380  10uF  [C805-35X60]  72.52 33.26 90 top
C381  0.1uF  [C402-25]  76.33 33.26 270 top
C382  0.1uF  [C402-25]  20.07 32.88 270 top
C383  10uF  [C805-35X60]  159.77 32.25 90 top
C384  10uF  [C805-35X60]  115.19 31.36 180 top
C385  0.1uF  [C402-25]  46.35 29.96 0 top
C386  0.01uF  [C402-25]  104.27 29.74 90 top
C387  0.1uF  [C402-25]  20.07 29.71 90 top
C388  1uF  [C402-25]  115.7 29.71 180 top
C389  1uF  [C402-25]  70.99 29.45 270 top
C390  10uF  [C805-35X60]  72.52 29.45 270 top
C391  0.1uF  [C402-25]  76.33 29.2 90 top
C392  0.1uF  [C402-25]  121.28 29.2 270 top
C393  0.1uF  [C402-25]  16.89 27.17 0 top
C394  0.1uF  [C402-25]  121.28 26.66 270 top
C395  10nF  [C402-25]  156.08 26.28 270 top
C396  4.7nF  [C402-25]  157.35 26.28 90 top
C397  0.1uF  [C402-25]  76.33 25.9 270 top
C398  10uF  [C805-35X60]  72.52 25.52 90 top
C399  1uF  [C402-25]  70.99 25.26 90 top
C400  10uF  [C805-35X60]  118.75 25.14 0 top
C401  0.22uF  [C201-6P6SPC]  129.41 25.01 270 top
C402  0.22uF  [C201-6P6SPC]  130.18 25.01 270 top
C403  0.22uF  [C603-35X45]  181.99 24.88 90 top
C404  0.22uF  [C603-35X45]  183.64 24.88 90 top
C405  10uF  [C805-35X60]  102.36 24.79 180 top
C406  0.1uF  [C402-25]  28.12 24.63 270 top
C407  0.1uF  [C402-25]  30.35 24.5 0 top
C408  0.1uF  [C402-25]  24.54 24.45 180 top
C409  10uF  [C805-35X60]  40.89 23.87 180 top
C410  0.1uF  [C402-25]  121.28 23.61 90 top
C411  0.22uF  [C201-6P6SPC]  138.43 23.36 270 top
C412  0.22uF  [C201-6P6SPC]  139.19 23.36 270 top
C413  0.22uF  [C201-6P6SPC]  132.46 23.23 270 top
C414  0.22uF  [C201-6P6SPC]  133.22 23.23 270 top
C415  4.7uF  [C805-35X60]  23.29 22.72 180 top
C416  4.7uF  [C805-35X60]  30.91 22.72 0 top
C417  0.01uF  [C402-25]  60.96 22.34 90 top
C418  0.01uF  [C402-25]  62.61 22.34 90 top
C419  0.01uF  [C402-25]  64.01 22.34 90 top
C420  0.01uF  [C402-25]  65.53 22.34 90 top
C421  0.01uF  [C402-25]  67.06 22.34 90 top
C422  0.01uF  [C402-25]  68.45 22.34 90 top
C423  10uF  [C805-35X60]  35.43 21.96 90 top
C424  10uF  [C805-35X60]  37.59 21.96 90 top
C425  0.22uF  [C201-6P6SPC]  135.51 21.71 270 top
C426  0.22uF  [C201-6P6SPC]  136.27 21.71 270 top
C427  0.22uF  [C201-6P6SPC]  141.35 21.71 270 top
C428  0.22uF  [C201-6P6SPC]  142.11 21.71 270 top
C429  0.01uF  [C402-25]  112.85 21.52 180 top
C430  0.1uF  [C402-25]  121.28 20.44 270 top
C431  4.7uF  [C805-35X60]  78.36 19.8 180 top
C432  0.01uF  [C402-25]  105.92 19.61 180 top
C433  0.01uF  [C402-25]  109.6 19.61 0 top
C434  0.01uF  [C402-25]  111.12 19.2 90 top
C435  1uF  [C402-25]  112.24 19.2 90 top
C436  10uF  [C1210-70X102]  154.43 19.04 180 top
C437  10uF  [C1210-70X102]  161.42 19.04 0 top
C438  10uF  [C805-35X60]  118.75 18.79 0 top
C439  0.22uF  [C603-35X45]  167.13 18.79 270 top
C440  4.7uF  [C805-35X60]  82.04 18.4 90 top
C441  27pF  [C402-25]  15.37 18.15 270 top
C442  100pF  [C402-25]  37.21 18.02 0 top
C443  10uF  [C805-35X60]  56.9 18.02 270 top
C444  10uF  [C805-35X60]  63.5 18.02 270 top
C445  1uF  [C402-25]  65.02 18.02 270 top
C446  1uF  [C402-25]  66.55 18.02 270 top
C447  10uF  [C805-35X60]  68.07 18.02 270 top
C448  0.22uF  [C603-35X45]  200.91 18.02 270 top
C449  27pF  [C402-25]  21.26 16.3 90 top
C450  10uF  [C1206-40X70]  152.15 15.74 0 top
C451  1000pF  [C402-25]  163.07 15.74 180 top
C452  0.1uF  [C402-25]  69.72 15.61 180 top
C453  0.1uF  [C402-25]  58.55 15.48 180 top
C454  0.1uF  [C402-25]  61.85 15.48 0 top
C455  10uF  [C1206-40X70]  100.33 14.72 0 top
C456  4.7uF  [C805-35X60]  13.77 13.71 180 top
C457  4.7uF  [C805-35X60]  117.22 13.71 270 top
C458  10uF  [C1206-40X70]  152.15 13.32 0 top
C459  4.7uF  [C805-35X60]  120.9 12.31 0 top
C460  10uF  [C1206-40X70]  79.5 8.63 0 top
C461  10uF  [C1206-40X70]  29.59 8.63 0 top
C462  10uF  [C1206-40X70]  46.23 8.63 0 top
C463  10uF  [C1206-40X70]  62.87 8.63 0 top
C464  4.7uF  [C805-35X60]  117.22 7.36 270 top
C465  0.1uF  [C402-25RD]  79.76 6.72 0 top
C466  1uF  [C603-35X45]  157.35 6.85 270 top
C467  4.7uF  [C603-35X45]  159.13 6.85 270 top
C468  NP  [C402-25]  162.56 6.85 270 top
C469  0.1uF  [C402-25RD]  29.84 6.72 0 top
C470  0.1uF  [C402-25RD]  46.48 6.72 0 top
C471  0.1uF  [C402-25RD]  63.12 6.72 0 top
C472  4.7uF  [C805-35X60]  120.9 6.09 0 top
C473  0.1uF  [C402-25RD]  79.76 5.2 0 top
C474  0.1uF  [C402-25RD]  29.84 5.2 0 top
C475  0.1uF  [C402-25RD]  46.48 5.2 0 top
C476  0.1uF  [C402-25RD]  63.12 5.2 0 top
C477  1uF  [C805-35X60]  173.99 5.07 180 top
C478  10uF  [C1206-40X70]  152.27 3.93 0 top
C479  10uF  [C1206-40X70]  79.5 3.42 0 top
C480  10uF  [C1206-40X70]  29.59 3.42 0 top
C481  10uF  [C1206-40X70]  46.23 3.42 0 top
C482  10uF  [C1206-40X70]  62.87 3.42 0 top
C483  10uF  [C1206-40X70]  99.82 3.29 0 top
C484  1nF  [C402-25]  181.99 142.74 0 bottom
C485  1nF  [C402-25]  179.83 142.74 180 bottom
C486  1nF  [C402-25]  171.83 142.74 0 bottom
C487  1nF  [C402-25]  169.67 142.74 180 bottom
C488  1uF  [C805-35X60]  182.88 141.09 180 bottom
C489  1uF  [C805-35X60]  179.71 141.09 0 bottom
C490  1uF  [C805-35X60]  172.72 141.09 180 bottom
C491  1uF  [C805-35X60]  169.54 141.09 0 bottom
C492  470pF  [C402-25]  107.19 134.86 270 bottom
C493  0.22uF  [C201-6P6SPC]  148.21 133.09 90 bottom
C494  0.22uF  [C201-6P6SPC]  147.45 133.09 90 bottom
C495  0.22uF  [C201-6P6SPC]  129.29 133.09 90 bottom
C496  0.22uF  [C201-6P6SPC]  128.52 133.09 90 bottom
C497  0.1uF  [C402-25]  133.99 129.28 270 bottom
C498  1uF  [C402-25]  130.94 129.28 90 bottom
C499  47pF  [C402-25]  113.54 127.5 180 bottom
C500  1uF  [C805-35X60]  183.51 123.56 270 bottom
C501  1uF  [C805-35X60]  178.44 123.56 270 bottom
C502  1uF  [C805-35X60]  175.77 123.56 270 bottom
C503  1uF  [C805-35X60]  170.81 123.56 270 bottom
C504  0.1uF  [C603-35X45]  181.61 120.77 180 bottom
C505  0.1uF  [C603-35X45]  175.9 120.77 0 bottom
C506  0.01uF  [C402-25]  109.22 120.64 270 bottom
C507  0.01uF  [C402-25]  106.43 120.64 270 bottom
C508  0.01uF  [C402-25]  103.38 120.64 270 bottom
C509  0.22uF  [C201-6P6SPC]  73.38 119.88 90 bottom
C510  0.22uF  [C201-6P6SPC]  72.59 119.88 90 bottom
C511  0.01uF  [C402-25]  110.74 119.12 180 bottom
C512  0.01uF  [C402-25]  102.11 118.86 0 bottom
C513  10uF  [C1210-70X102]  182.12 118.1 0 bottom
C514  10uF  [C1210-70X102]  175.26 118.1 180 bottom
C515  0.01uF  [C402-25]  110.74 117.59 180 bottom
C516  0.01uF  [C402-25]  102.11 116.83 0 bottom
C517  0.1uF  [C603-35X45]  186.44 116.7 270 bottom
C518  0.1uF  [C603-35X45]  170.94 116.58 270 bottom
C519  47uF  [CAP1210_2-75]  79.5 116.32 180 bottom
C520  47uF  [CAP1210_2-75]  73.66 116.32 0 bottom
C521  0.1uF  [C402-25]  128.91 116.19 90 bottom
C522  0.1uF  [C402-25]  44.2 115.94 90 bottom
C523  0.01uF  [C402-25]  110.74 115.05 180 bottom
C524  0.01uF  [C402-25]  102.11 113.78 0 bottom
C525  1uF  [C603-35X45]  179.96 113.65 180 bottom
C526  0.01uF  [C402-25]  110.74 113.65 180 bottom
C527  10uF  [CAP0805_1-5]  78.36 113.02 180 bottom
C528  10uF  [CAP0805_1-5]  74.8 113.02 0 bottom
C529  10uF  [C1210-70X102]  184.4 112.89 180 bottom
C530  10uF  [C1210-70X102]  174.5 112.89 0 bottom
C531  0.01uF  [C402-25]  108.2 112 90 bottom
C532  0.01uF  [C402-25]  107.19 112 90 bottom
C533  0.01uF  [C402-25]  106.17 112 90 bottom
C534  0.01uF  [C402-25]  103.89 112 90 bottom
C535  10uF  [CAP0805_1-5]  83.43 111 0 bottom
C536  2.2uF  [CAP0603_1]  79.63 109.59 180 bottom
C537  NP  [C402-25RD]  173.23 108.45 90 bottom
C538  2.2uF  [CAP0603_1]  82.93 108.45 0 bottom
C539  NP  [C402-25RD]  183.77 108.32 90 bottom
C540  NP  [C402-25RD]  181.48 108.32 90 bottom
C541  NP  [C402-25RD]  179.2 108.32 90 bottom
C542  NP  [C402-25RD]  176.91 108.32 90 bottom
C543  2.2uF  [CAP0603_1]  79.25 107.88 180 bottom
C544  2.2uF  [CAP0603_1]  79.25 106.54 180 bottom
C545  47uF  [CAP1210_2-75]  67.06 104.89 270 bottom
C546  2.2uF  [CAP0603_1]  80.01 104.38 180 bottom
C547  2.2uF  [CAP0603_1]  130.43 103.88 90 bottom
C548  0.1uF  [CAP0402_0-75]  132.84 103.37 90 bottom
C549  0.1uF  [CAP0402_0-75]  80.26 102.99 180 bottom
C550  2.2uF  [CAP0603_1]  76.91 102.97 0 bottom
C551  0.1uF  [C402-25]  44.07 101.46 0 bottom
C552  2.2uF  [CAP0603_1]  133.48 100.83 270 bottom
C553  0.1uF  [C402-25]  65.02 100.83 90 bottom
C554  47uF  [CAP1210_2-75]  121.54 100.32 270 bottom
C555  47uF  [CAP1210_2-75]  141.33 100.31 270 bottom
C556  2.2uF  [CAP0603_1]  131.44 100.07 270 bottom
C557  2.2uF  [CAP0603_1]  130.18 100.07 270 bottom
C558  2.2uF  [CAP0603_1]  128.91 100.07 270 bottom
C559  10uF  [CAP0805_1-5]  78.36 99.81 180 bottom
C560  10uF  [CAP0805_1-5]  74.8 99.81 0 bottom
C561  1000pF  [C402-25]  51.18 99.56 270 bottom
C562  0.1uF  [C402-25]  48.64 99.56 270 bottom
C563  10uF  [CAP0805_1-5]  138.05 99.18 270 bottom
C564  10uF  [CAP0805_1-5]  124.84 99.18 270 bottom
C565  22uF  [C1206-40X70]  61.59 99.18 270 bottom
C566  1000pF  [C402-25]  44.7 98.92 0 bottom
C567  1000pF  [C402-25]  44.7 97.91 0 bottom
C568  2.2uF  [CAP0603_1]  134.11 97.27 180 bottom
C569  47uF  [CAP1210_2-75]  79.5 96.51 180 bottom
C570  47uF  [CAP1210_2-75]  73.66 96.51 0 bottom
C571  0.1uF  [C402-25]  61.59 95.75 90 bottom
C572  10uF  [CAP0805_1-5]  138.05 95.62 90 bottom
C573  10uF  [CAP0805_1-5]  124.84 95.62 90 bottom
C574  0.1uF  [C402-25]  195.96 95.49 0 bottom
C575  220pF  [C402-25]  64.9 95.11 0 bottom
C576  47uF  [CAP1210_2-75]  141.35 94.48 90 bottom
C577  47uF  [CAP1210_2-75]  121.54 94.48 90 bottom
C578  0.1uF  [CAP0402_0-75]  133.35 93.72 90 bottom
C579  22uF  [C1206-40X70]  63.12 93.21 0 bottom
C580  0.1uF  [C402-25]  195.96 92.95 180 bottom
C581  2.2uF  [C603-35X45]  157.86 89.02 90 bottom
C582  47uF  [CAP1210_2-75]  132.97 87.87 0 bottom
C583  0.1uF  [C201-6P6SPC]  106.3 86.98 90 bottom
C584  0.1uF  [C201-6P6SPC]  104.9 86.98 90 bottom
C585  0.1uF  [C201-6P6SPC]  103.5 86.98 90 bottom
C586  0.47uF  [C402-25]  102.11 86.98 90 bottom
C587  0.47uF  [C402-25]  100.71 86.98 90 bottom
C588  0.47uF  [C402-25]  99.19 86.98 90 bottom
C589  0.1uF  [C201-6P6SPC]  97.79 86.98 90 bottom
C590  0.1uF  [C201-6P6SPC]  96.39 86.98 90 bottom
C591  0.1uF  [C201-6P6SPC]  95 86.98 90 bottom
C592  9pF  [CAP0402_0-75]  139.06 86.86 0 bottom
C593  9pF  [CAP0402_0-75]  136.91 86.86 180 bottom
C594  0.1uF  [C402-25]  158.5 86.1 270 bottom
C595  1uF  [EMIFIL_NFM15CC_0402_0-5]  109.6 85.59 270 bottom
C596  0.1uF  [C402-25]  34.92 85.33 180 bottom
C597  4.7uF  [C603-35X45]  156.21 85.21 180 bottom
C598  0.1uF  [C201-6P6SPC]  104.9 84.95 90 bottom
C599  0.1uF  [C201-6P6SPC]  103.5 84.95 90 bottom
C600  0.1uF  [C201-6P6SPC]  102.11 84.95 90 bottom
C601  0.47uF  [C402-25]  100.71 84.95 90 bottom
C602  0.47uF  [C402-25]  99.19 84.95 90 bottom
C603  0.1uF  [C201-6P6SPC]  97.79 84.95 90 bottom
C604  0.1uF  [C201-6P6SPC]  96.39 84.95 90 bottom
C605  0.1uF  [C201-6P6SPC]  95 84.95 90 bottom
C606  0.1uF  [C201-6P6SPC]  93.34 84.95 90 bottom
C607  0.1uF  [C402-25]  194.18 82.03 90 bottom
C608  0.22uF  [C603-35X45]  153.8 81.65 270 bottom
C609  2.2uF  [C603-35X45]  146.81 81.65 270 bottom
C610  0.1uF  [C201-6P6SPC]  113.41 80.51 0 bottom
C611  0.22uF  [C603-35X45]  156.21 80.13 180 bottom
C612  1uF  [CAP0402_0-75]  76.45 79.11 90 bottom
C613  22uF  [C805-35X60]  74.55 79.11 90 bottom
C614  1uF  [EMIFIL_NFM15CC_0402_0-5]  113 78.91 180 bottom
C615  0.1uF  [C201-6P6SPC]  99.24 78.89 90 bottom
C616  0.1uF  [C201-6P6SPC]  103.61 78.54 180 bottom
C617  0.1uF  [C201-6P6SPC]  101.22 78.52 180 bottom
C618  0.1uF  [C201-6P6SPC]  97.16 78.48 0 bottom
C619  0.1uF  [C201-6P6SPC]  95.25 78.09 270 bottom
C620  0.1uF  [C201-6P6SPC]  105.16 77.71 180 bottom
C621  0.1uF  [C201-6P6SPC]  96.39 77.71 0 bottom
C622  1uF  [C402-25]  93.98 77.71 0 bottom
C623  0.1uF  [C201-6P6SPC]  99.22 77.37 270 bottom
C624  0.1uF  [C201-6P6SPC]  100.78 77.36 270 bottom
C625  0.1uF  [C201-6P6SPC]  102.36 77.33 270 bottom
C626  0.1uF  [C201-6P6SPC]  97.54 77.33 270 bottom
C627  1uF  [C402-25]  92.71 77.33 90 bottom
C628  0.1uF  [C201-6P6SPC]  105.16 76.95 0 bottom
C629  0.1uF  [C201-6P6SPC]  96.39 76.95 180 bottom
C630  0.1uF  [C201-6P6SPC]  101.58 76.57 270 bottom
C631  0.1uF  [C201-6P6SPC]  95.2 76.57 270 bottom
C632  0.1uF  [C201-6P6SPC]  98.39 76.57 270 bottom
C633  0.1uF  [C201-6P6SPC]  104.01 76.49 90 bottom
C634  0.1uF  [C402-25]  131.19 76.06 180 bottom
C635  0.01uF  [C402-25]  128.02 76.06 180 bottom
C636  0.01uF  [C402-25]  125.22 76.06 180 bottom
C637  0.01uF  [C402-25]  123.06 76.06 180 bottom
C638  1uF  [C402-25]  96.39 76.06 0 bottom
C639  0.1uF  [C201-6P6SPC]  102.39 75.78 270 bottom
C640  1uF  [C402-25]  93.52 75.73 90 bottom
C641  0.1uF  [C201-6P6SPC]  104.79 75.73 90 bottom
C642  0.1uF  [C201-6P6SPC]  103.25 75.68 90 bottom
C643  0.1uF  [C201-6P6SPC]  101.28 75.34 180 bottom
C644  0.1uF  [C201-6P6SPC]  99.99 75.35 0 bottom
C645  10uF  [C1210-70X102]  192.53 75.05 270 bottom
C646  10uF  [C1210-70X102]  188.47 75.05 270 bottom
C647  10uF  [C1210-70X102]  184.4 75.05 270 bottom
C648  10uF  [C1210-70X102]  180.34 75.05 270 bottom
C649  0.1uF  [C201-6P6SPC]  95.5 75.05 315 bottom
C650  0.1uF  [C201-6P6SPC]  97.58 74.97 90 bottom
C651  0.1uF  [C201-6P6SPC]  104.01 74.92 90 bottom
C652  0.01uF  [C402-25]  131.19 74.54 180 bottom
C653  0.01uF  [C402-25]  128.65 74.54 180 bottom
C654  0.01uF  [C402-25]  125.86 74.54 0 bottom
C655  0.1uF  [C201-6P6SPC]  102.74 74.54 0 bottom
C657  0.1uF  [C201-6P6SPC]  101.23 74.53 0 bottom
C658  1uF  [C402-25]  93.16 74.18 315 bottom
C659  1uF  [C402-25]  105.18 74.13 135 bottom
C660  0.1uF  [C402-25]  151.26 74.03 270 bottom
C662  0.1uF  [C201-6P6SPC]  97.16 73.75 180 bottom
C663  0.1uF  [C201-6P6SPC]  101.85 73.47 315 bottom
C664  0.1uF  [C201-6P6SPC]  95.61 73.75 180 bottom
C665  0.1uF  [C201-6P6SPC]  103.58 73.75 0 bottom
C666  10uF  [C603-35X45]  134.37 73.14 270 bottom
C667  0.1uF  [C402-25]  95 72.86 0 bottom
C668  0.1uF  [C201-6P6SPC]  101.6 72.51 90 bottom
C669  0.1uF  [C201-6P6SPC]  99.98 72.53 90 bottom
C670  0.1uF  [C201-6P6SPC]  105.54 72.38 90 bottom
C671  0.1uF  [C201-6P6SPC]  110.74 72.13 0 bottom
C672  0.1uF  [C201-6P6SPC]  104.39 72.13 0 bottom
C673  0.1uF  [C201-6P6SPC]  98.04 72.13 180 bottom
C674  0.1uF  [C201-6P6SPC]  96.39 72.13 180 bottom
C675  22uF  [C805-35X60]  66.29 72.13 90 bottom
C676  22uF  [C805-35X60]  62.48 72.13 90 bottom
C677  0.1uF  [C201-6P6SPC]  102.74 71.74 45 bottom
C678  1uF  [CAP0402_0-75]  68.07 72 90 bottom
C679  1uF  [CAP0402_0-75]  64.39 72 90 bottom
C680  1uF  [C402-25]  93.18 71.75 45 bottom
C681  0.1uF  [C402-25]  195.33 71.74 270 bottom
C682  0.01uF  [C402-25]  132.72 71.74 90 bottom
C683  0.01uF  [C402-25]  121.54 71.49 90 bottom
C684  0.1uF  [C201-6P6SPC]  105.92 71.36 180 bottom
C685  0.1uF  [C201-6P6SPC]  100.46 71.36 0 bottom
C686  0.1uF  [C201-6P6SPC]  97.92 71.36 0 bottom
C687  0.1uF  [C201-6P6SPC]  96.39 71.36 0 bottom
C688  0.1uF  [C201-6P6SPC]  94.74 71.36 0 bottom
C689  0.1uF  [C201-6P6SPC]  104.78 70.98 270 bottom
C690  0.1uF  [C201-6P6SPC]  104.05 70.94 90 bottom
C691  0.1uF  [C201-6P6SPC]  101.59 70.97 270 bottom
C692  0.1uF  [C201-6P6SPC]  103.19 70.97 270 bottom
C693  0.1uF  [C201-6P6SPC]  100.46 70.6 180 bottom
C694  0.1uF  [C201-6P6SPC]  97.92 70.47 180 bottom
C695  0.1uF  [C201-6P6SPC]  96.39 70.47 180 bottom
C696  0.1uF  [C201-6P6SPC]  94.74 70.47 180 bottom
C697  10uF  [C603-35X45]  134.37 70.35 270 bottom
C698  0.1uF  [C201-6P6SPC]  105.54 70.09 270 bottom
C699  0.1uF  [C201-6P6SPC]  102.03 69.74 180 bottom
C700  0.1uF  [C201-6P6SPC]  93.13 69.73 0 bottom
C701  0.1uF  [C201-6P6SPC]  97.92 69.71 0 bottom
C702  0.1uF  [C201-6P6SPC]  96.39 69.71 0 bottom
C703  0.1uF  [C201-6P6SPC]  94.74 69.71 0 bottom
C704  0.1uF  [C201-6P6SPC]  103.71 69.48 225 bottom
C705  0.01uF  [C402-25]  132.72 69.33 270 bottom
C706  0.1uF  [C201-6P6SPC]  104.78 69.33 270 bottom
C707  0.1uF  [C201-6P6SPC]  100.79 69.33 270 bottom
C708  0.1uF  [C201-6P6SPC]  99.97 69.33 270 bottom
C709  0.1uF  [C201-6P6SPC]  105.92 68.95 0 bottom
C710  0.1uF  [C201-6P6SPC]  98.04 68.95 180 bottom
C711  0.1uF  [C201-6P6SPC]  95.5 68.95 0 bottom
C712  0.1uF  [C201-6P6SPC]  93.98 68.95 0 bottom
C713  10uF  [C1210-70X102]  176.78 68.7 0 bottom
C714  0.1uF  [C201-6P6SPC]  102.45 68.46 90 bottom
C715  0.1uF  [C201-6P6SPC]  101.58 68.43 90 bottom
C716  0.1uF  [C201-6P6SPC]  105.16 68.19 0 bottom
C717  0.1uF  [C201-6P6SPC]  103.63 68.19 0 bottom
C718  0.1uF  [C201-6P6SPC]  94.74 68.19 0 bottom
C719  0.1uF  [C201-6P6SPC]  92.33 68.19 180 bottom
C720  0.1uF  [C201-6P6SPC]  100.38 68.14 0 bottom
C722  0.1uF  [C201-6P6SPC]  96.39 68.06 0 bottom
C723  0.1uF  [C201-6P6SPC]  93.6 67.73 90 bottom
C724  0.1uF  [C201-6P6SPC]  94.74 67.48 180 bottom
C725  0.1uF  [C201-6P6SPC]  105.16 67.3 180 bottom
C726  0.1uF  [C201-6P6SPC]  103.5 67.3 180 bottom
C727  0.1uF  [C201-6P6SPC]  101.98 67.3 180 bottom
C728  0.1uF  [C201-6P6SPC]  100.46 67.3 180 bottom
C730  0.1uF  [C201-6P6SPC]  96.39 67.3 180 bottom
C731  0.1uF  [C201-6P6SPC]  92.79 66.92 90 bottom
C732  1uF  [C402-25]  91.97 66.92 270 bottom
C733  0.01uF  [C402-25]  135 66.54 270 bottom
C734  0.01uF  [C402-25]  133.48 66.54 270 bottom
C735  0.1uF  [C201-6P6SPC]  106.05 66.54 180 bottom
C736  0.1uF  [C201-6P6SPC]  103.63 66.54 0 bottom
C737  1uF  [C402-25]  96.43 66.4 0 bottom
C738  0.1uF  [C201-6P6SPC]  102.38 66.17 90 bottom
C739  0.1uF  [C201-6P6SPC]  104.78 66.16 270 bottom
C740  0.1uF  [C201-6P6SPC]  93.6 66.16 90 bottom
C741  0.1uF  [C201-6P6SPC]  98.42 66.15 90 bottom
C742  1uF  [C402-25]  94.78 66.15 225 bottom
C743  0.1uF  [C201-6P6SPC]  101.59 66.14 270 bottom
C744  0.1uF  [C201-6P6SPC]  100.75 66.13 90 bottom
C745  0.1uF  [C201-6P6SPC]  106.05 65.78 0 bottom
C746  10pF  [C402-25]  41.27 65.78 270 bottom
C747  0.1uF  [C201-6P6SPC]  95.62 65.49 0 bottom
C748  0.1uF  [C201-6P6SPC]  97.22 65.5 0 bottom
C749  10pF  [C402-25]  42.42 65.39 90 bottom
C750  10nF  [C402-25]  37.72 65.01 90 bottom
C751  1uF  [C402-25]  36.45 65.01 90 bottom
C752  0.1uF  [C201-6P6SPC]  101.97 64.92 0 bottom
C753  0.1uF  [C201-6P6SPC]  97.94 64.89 0 bottom
C754  10uF  [C1210-70X102]  176.78 64.89 0 bottom
C755  0.1uF  [C201-6P6SPC]  105.16 64.89 0 bottom
C756  0.1uF  [C201-6P6SPC]  99.99 64.51 270 bottom
C757  0.1uF  [C201-6P6SPC]  96.77 64.51 90 bottom
C758  0.01uF  [C402-25]  121.54 64 270 bottom
C759  0.01uF  [C402-25]  132.72 63.62 90 bottom
C760  0.01uF  [C402-25]  135 63.36 270 bottom
C761  0.01uF  [C402-25]  121.67 61.58 270 bottom
C762  0.01uF  [C402-25]  132.72 61.08 270 bottom
C763  0.1uF  [C201-6P6SPC]  111.07 61.03 90 bottom
C764  0.01uF  [C402-25]  135 60.19 270 bottom
C765  0.1uF  [C402-25]  58.29 59.68 90 bottom
C766  100nF  [C402-25]  38.23 59.3 0 bottom
C767  0.01uF  [C402-25]  129.92 59.17 0 bottom
C768  NP-10nF  [C402-25]  43.69 59.04 180 bottom
C769  0.1uF  [C603-35X45]  172.34 58.79 90 bottom
C770  0.01uF  [C402-25]  124.71 58.41 180 bottom
C771  0.1uF  [C402-25]  134.62 58.28 0 bottom
C772  0.01uF  [C402-25]  132.46 58.28 180 bottom
C773  0.1uF  [C201-6P6SPC]  95.03 57.92 270 bottom
C774  0.01uF  [C402-25]  129.79 57.01 180 bottom
C775  0.01uF  [C402-25]  127.38 57.01 180 bottom
C776  0.01uF  [C402-25]  125.22 57.01 180 bottom
C777  0.01uF  [C402-25]  122.94 57.01 180 bottom
C778  4700pF  [C402-25]  21.59 56.25 180 bottom
C779  100nF  [C402-25]  40.26 56.12 90 bottom
C780  NP-100nF  [C402-25]  41.66 56 90 bottom
C781  0.1uF  [C402-25]  57.02 54.09 270 bottom
C782  0.1uF  [C201-6P6SPC]  80.9 52.69 90 bottom
C783  1uF  [C402-25]  40.13 52.19 270 bottom
C784  10nF  [C402-25]  38.86 52.19 270 bottom
C785  0.1uF  [C402-25]  30.23 51.93 90 bottom
C786  0.1uF  [C402-25]  27.69 51.93 270 bottom
C787  0.1uF  [C402-25]  27.69 46.6 270 bottom
C788  4700pF  [C402-25RD]  21.59 44.44 180 bottom
C789  0.1uF  [C402-25]  43.43 37.84 0 bottom
C790  0.1uF  [C402-25]  41.27 37.84 180 bottom
C791  0.01uF  [C402-25]  62.87 32.63 90 bottom
C792  0.01uF  [C402-25]  68.83 32.5 90 bottom
C793  1uF  [C402-25]  58.29 30.85 180 bottom
C794  0.1uF  [C402-25]  43.43 30.72 0 bottom
C795  0.1uF  [C402-25]  41.27 30.72 180 bottom
C796  0.01uF  [C402-25]  58.29 29.83 180 bottom
C797  0.01uF  [C402-25]  104.9 29.74 90 bottom
C798  1uF  [C402-25]  103.59 29.74 90 bottom
C799  0.01uF  [C402-25]  113.28 29.49 90 bottom
C800  0.01uF  [C402-25]  70.87 29.45 270 bottom
C801  0.01uF  [C402-25]  111.56 29.03 0 bottom
C802  0.01uF  [C402-25]  58.29 28.82 180 bottom
C803  0.01uF  [C402-25]  70.74 25.14 90 bottom
C804  0.01uF  [C402-25]  102.36 24.79 180 bottom
C805  0.1uF  [C402-25RD]  74.17 24.12 0 bottom
C806  1uF  [C402-25]  116 23.51 90 bottom
C807  0.01uF  [C402-25]  114.86 23.51 90 bottom
C808  0.1uF  [C402-25RD]  74.17 23.1 0 bottom
C809  0.01uF  [C402-25]  71.37 22.72 0 bottom
C810  0.01uF  [C402-25]  58.17 22.6 180 bottom
C811  0.1uF  [C402-25]  17.2 21.83 270 bottom
C812  0.01uF  [C402-25]  71.37 21.71 0 bottom
C813  0.01uF  [C402-25]  58.17 21.58 180 bottom
C814  1uF  [C402-25]  58.17 20.44 180 bottom
C815  1uF  [C402-25]  116.33 19.03 270 bottom
C816  0.01uF  [C402-25]  115.19 19.03 270 bottom
C817  0.1uF  [C402-25]  101.22 18.82 180 bottom
C818  0.047uF  [C402-25RD]  65.41 18.53 270 bottom
C819  0.047uF  [C402-25RD]  64.14 18.53 270 bottom
C820  0.01uF  [C402-25]  102.97 18.42 270 bottom
C821  0.1uF  [C402-25]  95.41 17.93 0 bottom
C822  0.047uF  [C402-25RD]  58.93 17.9 180 bottom
C823  0.1uF  [C402-25RD]  70.61 17.77 0 bottom
C824  0.01uF  [C402-25]  109.22 17.01 270 bottom
C825  0.1uF  [C402-25RD]  58.93 16.88 180 bottom
C826  0.01uF  [C402-25]  114.05 16.79 270 bottom
C827  0.047uF  [C402-25RD]  70.61 16.75 0 bottom
C828  0.01uF  [C402-25]  110.49 16.28 270 bottom
C829  0.047uF  [C402-25RD]  58.93 15.74 180 bottom
C830  0.1uF  [C402-25RD]  70.61 15.61 0 bottom
C831  0.1uF  [C402-25]  109.22 14.98 270 bottom
C832  0.1uF  [C402-25]  108.2 14.98 270 bottom
C833  10uF  [C805-35X60]  127.32 14.86 180 bottom
C834  0.1uF  [C402-25RD]  58.93 14.72 180 bottom
C835  0.047uF  [C402-25RD]  70.61 14.59 0 bottom
C836  0.1uF  [C402-25]  127.6 13.21 180 bottom
C837  0.1uF  [C603-35X45]  187.96 10.78 180 bottom
C838  0.1uF  [C603-35X45]  185.29 10.02 270 bottom
C839  0.1uF  [C402-25]  149.48 72 180 top
D1  LED_GRN  [LED1206-59X59]  65.15 143.88 90 top
D2  ESD DIODE  [ESD402]  41.91 140.32 0 top
D3  ESD DIODE  [ESD402]  52.45 139.31 180 top
D4  BZX84C6V8LT1G  [SOT23-123_1-2]  143.51 135.12 270 top
D5  ESD DIODE  [ESD402]  26.29 132.07 90 top
D6  SZMM3Z10VST1G  [DIO_SOD323_1-1]  153.75 94.19 180 top
D7  B170-13-F  [SMA2-78SQ]  185.04 87.87 90 top
D8  PMEG6010CEJ,115  [SOD323]  188.85 83.56 90 top
D9  CUS05S40,H3F  [SOD323]  181.36 57.39 90 top
D10  MMSZ5237BS-7-F  [SOD323]  178.94 54.98 90 top
D11  BAS516,115  [SOD523]  181.36 52.82 90 top
D12  BAS516,115  [SOD523]  181.48 47.74 270 top
D13  BAT54HT1G  [SOD323]  194.18 43.3 0 top
D14  LED_GRN  [LED1206-59X59]  13.59 28.44 270 top
D15  TPD1E05U06DPY  [DPY]  131.83 18.44 180 top
D16  TPD1E05U06DPY  [DPY]  133.86 18.44 0 top
D17  TPD1E05U06DPY  [DPY]  139.81 18.44 0 top
D18  TPD1E05U06DPY  [DPY]  137.77 18.44 180 top
D19  TPD1E05U06DPY  [DPY]  128.78 16.79 180 top
D20  TPD1E05U06DPY  [DPY]  130.81 16.79 0 top
D21  TPD1E05U06DPY  [DPY]  134.85 16.79 180 top
D22  TPD1E05U06DPY  [DPY]  136.89 16.79 0 top
D23  TPD1E05U06DPY  [DPY]  140.7 16.79 180 top
D24  TPD1E05U06DPY  [DPY]  142.73 16.79 0 top
D25  SMBJ14A  [SMB-UNI]  191.01 14.34 180 bottom
D26  SMBJ36A  [SMB-UNI]  184.15 14.34 0 bottom
DS1  LED_GRN  [LED1206-59X59]  162.18 3.29 0 top
FL1  DLW21SN121HQ2  [EMI-36X15-DLW21]  132.72 138.42 90 top
FL2  DLW21SN121HQ2  [EMI-36X15-DLW21]  70.99 129.78 270 top
FL3  DLW21SN121HQ2  [EMI-36X15-DLW21]  149.48 126.86 90 top
FL4  120E  [EMIFIL_BLM18A_0603]  99.19 122.16 180 top
FL5  120E  [EMIFIL_BLM18A_0603]  96.65 115.43 180 top
FL6  120E  [L603-35X45]  94.36 103.24 180 top
FL7  120E  [L603-35X45]  103.12 101.21 180 top
FL8  120E  [L603-35X45]  107.7 100.19 180 top
FL9  120E  [L603-35X45]  104.39 94.22 0 top
FL10  120E  [L603-35X45]  112.78 94.1 180 top
FL11  120E  [L603-35X45]  91.19 93.97 0 top
FL12  120E  [EMIFIL_BLM18A_0603]  28.07 81.02 180 top
FL13  120E  [EMIFIL_BLM18A_0603]  34.67 65.65 90 top
FL14  120E  [EMIFIL_BLM18A_0603]  27.94 64.51 180 top
FL15  120E  [L603-35X45]  111.38 53.08 180 top
FL16  120E  [EMIFIL_BLM18A_0603]  37.21 51.55 90 top
FL17  120E  [L603-35X45]  97.54 46.34 0 top
FL18  120E  [L603-35X45]  102.36 46.34 0 top
FL19  120E  [L603-35X45]  89.08 42.71 0 top
FL20  120E  [EMIFIL_BLM18A_0603]  74.68 33.26 270 top
FL21  120E  [EMIFIL_BLM18A_0603]  118.75 29.71 180 top
FL22  120E  [EMIFIL_BLM18A_0603]  74.68 29.45 90 top
FL23  120E  [EMIFIL_BLM18A_0603]  118.75 27.17 180 top
FL24  120E  [EMIFIL_BLM18A_0603]  74.68 25.64 270 top
FL25  120E  [EMIFIL_BLM18A_0603]  118.77 23.09 180 top
FL26  DLW21SN900HQ2  [EMI-36X15-DLW21-RDPADS]  129.79 22.61 270 top
FL27  120E  [EMIFIL_BLM18A_0603]  118.75 20.94 180 top
FL28  DLW21SN900HQ2  [EMI-36X15-DLW21-RDPADS]  138.79 20.98 270 top
FL29  DLW21SN900HQ2  [EMI-36X15-DLW21-RDPADS]  132.84 20.98 270 top
FL30  DLW21SN900HQ2  [EMI-36X15-DLW21-RDPADS]  135.87 19.33 270 top
FL31  DLW21SN900HQ2  [EMI-36X15-DLW21-RDPADS]  141.71 19.33 270 top
FL32  120E  [EMIFIL_BLM18A_0603]  59.05 18.02 90 top
FL33  120E  [EMIFIL_BLM18A_0603]  61.34 18.02 90 top
FL34  120E  [EMIFIL_BLM18A_0603]  70.23 18.02 90 top
FL35  DLW21SN900HQ2  [EMI-36X15-DLW21-RDPADS]  147.83 135.63 90 bottom
FL36  DLW21SN900HQ2  [EMI-36X15-DLW21-RDPADS]  145.8 135.63 90 bottom
FL37  DLW21SN900HQ2  [EMI-36X15-DLW21-RDPADS]  128.91 135.63 90 bottom
FL38  DLW21SN900HQ2  [EMI-36X15-DLW21-RDPADS]  126.87 135.63 90 bottom
FL39  120E  [L603-35X45]  72.64 79.11 270 bottom
FL40  0.47uF  [EMI-NFM21P]  98.42 17.93 0 bottom
FL41  DLW21SN900HQ2  [EMI-36X15-DLW21-RDPADS]  108.71 12.18 270 bottom
HS1  HS-DDV44  [HS-DKQ56]  178.69 117.46 270 top
J1  1932258-1-USB3  [CON-1932258]  127.76 143.37 180 top
J2  1932258-1-USB3  [CON-1932258]  146.69 143.37 180 top
J3  1725711  [CONN-1725711]  169.8 149.34 0 top
J4  1725656  [CONN-1725656]  20.19 148.33 180 top
J5  FAKRA II  [CONN-ST-FAKRA]  39.37 147.44 180 top
